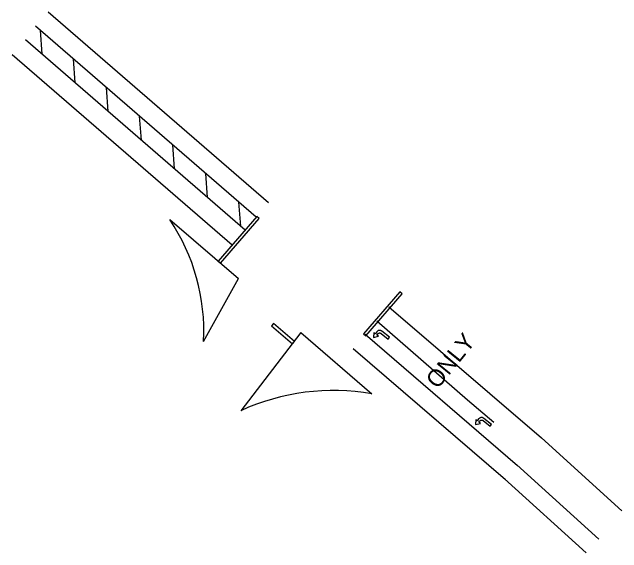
# Model space of a CAD drawing. Extents: x 973881 to 978318, y 704121 to 707549.
# Drawn here: x 973881.3 to 974274.7, y 707199.4 to 707548.5 of the extents above; entities that cross this region are included whole.
import ezdxf

# ---------------------------------------------------------------- set-up
doc = ezdxf.new("R2010")
doc.units = 0
doc.layers.add('R_Striping', color=7, linetype='Continuous')

msp = doc.modelspace()

# ---------------------------------------------------------------- linework, layer by layer
at = {"layer": 'R_Striping'}
for p, q in [((974046.71, 707425.36), (973904.51, 707548.51)), ((974038.75, 707416.17), (973896.38, 707539.47)), ((973900.55, 707521.3), (973899.45, 707536.81)), ((974031.54, 707407.86), (973889.82, 707530.59)), ((974023.12, 707398.16), (973881.27, 707521.02)), ((973921.91, 707502.8), (973920.81, 707518.31)), ((973943.27, 707484.3), (973942.17, 707499.81)), ((973964.63, 707465.8), (973963.53, 707481.31)), ((973985.99, 707447.3), (973984.89, 707462.81)), ((974007.35, 707428.8), (974006.26, 707444.31)), ((974028.72, 707410.3), (974027.62, 707425.81)), ((973983.01, 707414.54), (974027.23, 707376.65)), ((974004.8, 707335.96), (974027.23, 707376.65)), ((974124.39, 707358.29), (974222.74, 707273.56)), ((974067.58, 707341.62), (974028.85, 707291.19)), ((974067.58, 707341.62), (974113.37, 707302.02)), ((974109.06, 707340.5), (974207.41, 707255.77)), ((974101.23, 707331.41), (974199.58, 707246.68)), ((974222.74, 707273.56), (974274.66, 707226.49)), ((974206.97, 707256.17), (974259.75, 707208.31)), ((974198.91, 707247.28), (974251.69, 707199.42))]:
    msp.add_line(p, q, dxfattribs=at)
for points in [[(974015.75, 707386.47), (974040.6, 707415.22), (974039.07, 707416.54), (974014.22, 707387.79)], [(974109.5, 707339.46), (974132.96, 707366.6), (974131.43, 707367.92), (974107.97, 707340.78)], [(974048.68, 707345.98), (974062.08, 707334.46), (974063.39, 707335.97), (974049.98, 707347.5)], [(974124.73, 707338.58), (974119.9, 707342.49), (974119.65, 707342.67), (974119.45, 707342.78), (974119.16, 707342.9), (974118.92, 707342.97), (974118.64, 707343.02), (974118.11, 707343.02), (974117.83, 707342.97), (974117.5, 707342.87), (974117.17, 707342.72), (974116.95, 707342.58), (974116.77, 707342.43), (974116.47, 707342.12), (974115.5, 707340.92), (974114.55, 707341.69), (974114.47, 707338.49), (974117.59, 707339.23), (974116.64, 707340), (974117.3, 707340.82), (974117.42, 707340.96), (974117.6, 707341.1), (974117.84, 707341.24), (974118.02, 707341.31), (974118.14, 707341.34), (974118.29, 707341.36), (974118.47, 707341.37), (974118.6, 707341.36), (974118.78, 707341.33), (974118.96, 707341.3), (974119.03, 707341.24), (974119.18, 707341.17), (974119.36, 707341.04), (974123.81, 707337.44)], [(974190.54, 707282.34), (974185.72, 707286.24), (974185.46, 707286.42), (974185.26, 707286.53), (974184.97, 707286.66), (974184.73, 707286.72), (974184.46, 707286.77), (974183.92, 707286.77), (974183.64, 707286.73), (974183.31, 707286.63), (974182.98, 707286.47), (974182.76, 707286.33), (974182.58, 707286.19), (974182.28, 707285.88), (974181.31, 707284.68), (974180.36, 707285.45), (974180.28, 707282.25), (974183.4, 707282.99), (974182.45, 707283.76), (974183.11, 707284.58), (974183.24, 707284.71), (974183.41, 707284.86), (974183.65, 707284.99), (974183.83, 707285.06), (974183.95, 707285.09), (974184.1, 707285.12), (974184.28, 707285.12), (974184.41, 707285.12), (974184.59, 707285.08), (974184.77, 707285.05), (974184.85, 707285), (974184.99, 707284.92), (974185.17, 707284.8), (974189.62, 707281.2)]]:
    msp.add_lwpolyline(points, close=True, dxfattribs=at)
msp.add_lwpolyline([(974116.52, 707349.23), (974175.11, 707298.23), (974192.13, 707283.79)], dxfattribs=at)
for centre, radius, start, end in [((973875.46, 707342.41), 129.5, 357.1454, 33.8487), ((974088.39, 707161.73), 142.5, 79.9031, 114.6954)]:
    msp.add_arc(centre, radius, start, end, dxfattribs=at)

# ---------------------------------------------------------------- texts
msp.add_text('ONLY', height=10.862, rotation=51.0351, dxfattribs=at).set_placement((974155.8, 707304.72))

doc.saveas('drawing.dxf')
